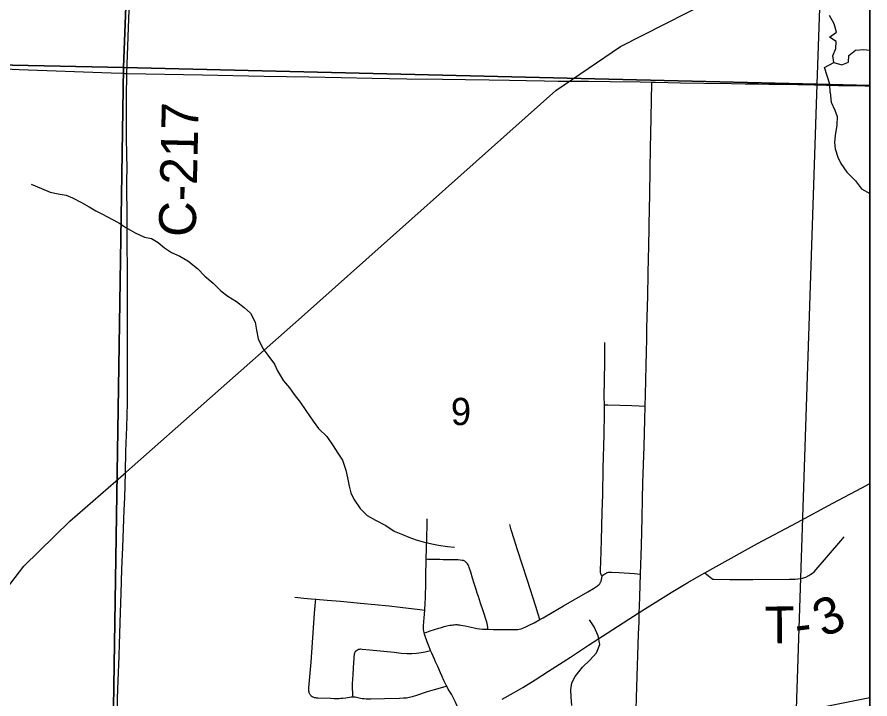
# Model space of a CAD drawing. Extents: x 0 to 34, y 0 to 22.
# Drawn here: x 7.587 to 8.9, y 18.594 to 19.643 of the extents above; entities that cross this region are included whole.
import ezdxf

# ---------------------------------------------------------------- set-up
doc = ezdxf.new("R2010")
doc.units = 0
for name, color, linetype in [('GM_X_Corporation', 7, 'Continuous'), ('GM_X_County_Road', 7, 'Continuous'), ('GM_X_County_Road_Text', 7, 'Continuous'), ('GM_X_Minor_River', 7, 'Continuous'), ('GM_X_Rail_Line', 7, 'Continuous'), ('GM_X_Section_Text', 7, 'Continuous'), ('GM_X_Township_Road', 7, 'Continuous'), ('GM_X_Township_Road_Text', 7, 'Continuous'), ('GM_X_US_Route', 7, 'Continuous'), ('SH_Data', 7, 'Continuous')]:
    doc.layers.add(name, color=color, linetype=linetype)

msp = doc.modelspace()

# ---------------------------------------------------------------- linework, layer by layer
at = {"layer": 'GM_X_Corporation'}
for points in [[(8.9, 14.4942), (8.9, 20.9), (2.1, 20.9)], [(8.9, 14.4942), (8.9, 20.5041)]]:
    msp.add_lwpolyline(points, dxfattribs=at)
for points in [[(6.788, 20.5454), (7.7872, 20.529), (7.7504, 19.5655), (6.7486, 19.5865)], [(7.7872, 20.529), (8.792, 20.506), (8.8523, 20.5047), (8.8184, 19.5395), (7.7504, 19.5655)], [(8.9, 19.5378), (8.9, 20.5036), (8.8523, 20.5047), (8.8184, 19.5395)], [(6.7486, 19.5865), (7.7504, 19.5655), (7.7346, 18.5471), (6.72, 18.5734), (6.7472, 19.5762)], [(8.8184, 19.5395), (8.7846, 18.5318), (7.7346, 18.5471), (7.7504, 19.5655)], [(8.9, 18.5295), (8.9, 19.5378), (8.8184, 19.5395), (8.7846, 18.5318)]]:
    msp.add_lwpolyline(points, close=True, dxfattribs=at)
at = {"layer": 'GM_X_County_Road'}
for points in [[(7.7558, 19.5562), (7.758, 19.6264), (7.7595, 19.6668), (7.7619, 19.7283), (7.7639, 19.7923), (7.7668, 19.8662), (7.7707, 19.9768), (7.7744, 20.0693), (7.7761, 20.1203), (7.7788, 20.1874), (7.7812, 20.2483), (7.7819, 20.2659)], [(7.7523, 18.9034), (7.7529, 18.9215), (7.7534, 18.9426), (7.7543, 18.975), (7.7555, 19.0116), (7.7564, 19.0489), (7.7567, 19.0862), (7.7567, 19.1278), (7.7568, 19.1626), (7.7568, 19.208), (7.7566, 19.2447), (7.7561, 19.3031), (7.7562, 19.3305), (7.7558, 19.3895), (7.7559, 19.4125), (7.7558, 19.4293), (7.7553, 19.4592), (7.7552, 19.4902), (7.7552, 19.5226), (7.7557, 19.5531), (7.7558, 19.5562)], [(7.7405, 18.5671), (7.7408, 18.5697), (7.741, 18.5721), (7.7413, 18.5935), (7.7418, 18.6088), (7.7423, 18.6215), (7.7438, 18.6593), (7.7441, 18.678), (7.746, 18.7265), (7.7471, 18.7563), (7.7481, 18.7929), (7.7494, 18.8271), (7.7517, 18.8842), (7.7523, 18.9034)]]:
    msp.add_lwpolyline(points, dxfattribs=at)
at = {"layer": 'GM_X_Minor_River'}
for points in [[(8.8446, 19.5732), (8.8426, 19.5835), (8.8474, 19.5948), (8.8481, 19.6054), (8.8376, 19.6121), (8.8484, 19.6198), (8.845, 19.6324), (8.8377, 19.6455)], [(8.839, 19.5269), (8.8381, 19.5399), (8.8343, 19.5525), (8.83, 19.5656), (8.8446, 19.5732), (8.8567, 19.5695), (8.867, 19.5734), (8.8677, 19.584), (8.8777, 19.5921), (8.8907, 19.5929), (8.9, 19.5921)], [(8.839, 19.5269), (8.8405, 19.5121), (8.8459, 19.4999), (8.8495, 19.4899), (8.8489, 19.4767), (8.8463, 19.4608), (8.8454, 19.4502), (8.8463, 19.4403), (8.8506, 19.4273), (8.8554, 19.4177), (8.8646, 19.4043), (8.8776, 19.3911), (8.8868, 19.3784), (8.9, 19.3717), (8.9, 19.3717)], [(7.6082, 19.3857), (7.6244, 19.3789), (7.6376, 19.3733), (7.6501, 19.3712), (7.6621, 19.3687), (7.6719, 19.3647), (7.6858, 19.3576), (7.6974, 19.3509), (7.708, 19.345), (7.7181, 19.3395), (7.7327, 19.3317), (7.7432, 19.3261), (7.7541, 19.3191), (7.7683, 19.3108), (7.783, 19.3045), (7.7936, 19.302), (7.8041, 19.2961), (7.8138, 19.2876), (7.8243, 19.2809), (7.8374, 19.275), (7.8498, 19.2679), (7.8644, 19.2559), (7.8759, 19.2442), (7.8886, 19.2337), (7.9005, 19.2218), (7.911, 19.2136), (7.9244, 19.205), (7.9364, 19.196), (7.9461, 19.1871), (7.953, 19.1733), (7.9551, 19.1611), (7.9578, 19.1478), (7.9651, 19.1328), (7.9725, 19.1228), (7.9829, 19.109), (7.9876, 19.0986), (7.9968, 19.0829), (8.0061, 19.0721), (8.0134, 19.0621), (8.0223, 19.0501), (8.0312, 19.0374), (8.0426, 19.0209), (8.0507, 19.0097), (8.0634, 18.9973), (8.0734, 18.9831), (8.0807, 18.972), (8.0877, 18.9612), (8.0931, 18.9455), (8.0952, 18.9337), (8.0979, 18.9208), (8.1008, 18.9108), (8.1051, 18.9009), (8.1147, 18.8867), (8.1259, 18.8758), (8.1386, 18.8687), (8.1544, 18.8605), (8.1675, 18.8519), (8.1799, 18.8467), (8.1901, 18.8427), (8.201, 18.8383), (8.2119, 18.8351), (8.2252, 18.8321), (8.2357, 18.83), (8.2493, 18.8279), (8.26, 18.8273)], [(8.4411, 18.5836), (8.4398, 18.5965), (8.4396, 18.6075), (8.441, 18.6185), (8.4461, 18.6282), (8.4574, 18.6424), (8.4686, 18.6532), (8.479, 18.6644), (8.4838, 18.6772), (8.4814, 18.6906), (8.4752, 18.7043), (8.4679, 18.7155)]]:
    msp.add_lwpolyline(points, dxfattribs=at)
at = {"layer": 'GM_X_Rail_Line'}
for points in [[(7.4231, 18.1406), (7.4319, 18.4427), (7.4457, 18.5085), (7.4686, 18.5744), (7.4977, 18.6464), (7.5498, 18.7367), (7.5972, 18.798), (7.6677, 18.8669), (7.7503, 18.9389), (8.0244, 19.1809), (8.4163, 19.5301), (8.5159, 19.5976), (8.7545, 19.7191), (8.8502, 19.7708), (8.9, 19.7957)], [(2.1, 17.2578), (2.1839, 17.2743), (2.7373, 17.3807), (3.3215, 17.4979), (3.9612, 17.6228), (4.5554, 17.74), (5.1565, 17.8564), (5.7754, 17.979), (6.3342, 18.0908), (6.9022, 18.2018), (7.3492, 18.2882), (7.4239, 18.3027), (8.0092, 18.4168), (8.4623, 18.5082), (8.9, 18.5958)]]:
    msp.add_lwpolyline(points, dxfattribs=at)
at = {"layer": 'GM_X_Township_Road'}
for points in [[(7.5359, 19.5647), (7.59, 19.5625), (7.6322, 19.5609), (7.7316, 19.5572), (7.749, 19.5566), (7.7528, 19.5564), (7.7558, 19.5562)], [(7.7558, 19.5562), (7.8723, 19.5539), (7.9672, 19.5521), (8.0015, 19.5515), (8.0361, 19.5508), (8.0858, 19.55), (8.1334, 19.5492), (8.1868, 19.5481), (8.2418, 19.5475), (8.2774, 19.5469), (8.3135, 19.5464), (8.3451, 19.5459), (8.3709, 19.5454), (8.3987, 19.5449), (8.4198, 19.5446), (8.4317, 19.5445), (8.446, 19.5443), (8.4665, 19.5441), (8.4998, 19.5436), (8.546, 19.5431), (8.564, 19.5428)], [(8.561, 19.3673), (8.5616, 19.4111), (8.5628, 19.4664), (8.563, 19.4851), (8.5636, 19.5175), (8.5639, 19.5386), (8.564, 19.5428)], [(8.564, 19.5428), (8.5697, 19.5427), (8.6082, 19.5418), (8.6442, 19.5412), (8.687, 19.5406), (8.7079, 19.5404), (8.7283, 19.5401), (8.7443, 19.5399), (8.7672, 19.5396), (8.7746, 19.5395), (8.7889, 19.5392), (8.8144, 19.5386), (8.8517, 19.5379), (8.8927, 19.5372), (8.9, 19.5371)], [(8.5539, 19.0441), (8.5544, 19.0615), (8.5556, 19.1065), (8.556, 19.1276), (8.5563, 19.1475), (8.5566, 19.1643), (8.5578, 19.2137), (8.5587, 19.2476), (8.5591, 19.2719), (8.5595, 19.2895), (8.5607, 19.3504), (8.561, 19.3673)], [(8.4911, 19.0463), (8.4907, 19.0587), (8.4916, 19.1115), (8.4919, 19.1327), (8.4918, 19.142)], [(8.4874, 18.7825), (8.4867, 18.7837), (8.4861, 18.785), (8.4857, 18.786), (8.4854, 18.7867), (8.4853, 18.7874), (8.4852, 18.7884), (8.4851, 18.7903), (8.4851, 18.792), (8.4854, 18.8044), (8.4864, 18.8374), (8.4877, 18.8815), (8.4884, 18.9076), (8.4894, 18.9486), (8.4906, 19.0002), (8.4912, 19.0338), (8.4911, 19.045), (8.4911, 19.0463)], [(8.4911, 19.0463), (8.4964, 19.0461), (8.5332, 19.0452), (8.5445, 19.0446), (8.5539, 19.0441)], [(8.5467, 18.7858), (8.548, 18.8299), (8.5493, 18.8722), (8.5499, 18.9008), (8.5505, 18.9262), (8.5521, 18.9822), (8.5532, 19.0238), (8.5539, 19.0441)], [(8.2165, 18.8084), (8.2175, 18.8424), (8.2179, 18.861), (8.2182, 18.8709)], [(8.3918, 18.7158), (8.3893, 18.7241), (8.3856, 18.736), (8.3728, 18.7756), (8.3649, 18.7992), (8.3573, 18.8228), (8.3521, 18.8394), (8.3475, 18.854), (8.3453, 18.8618)], [(8.6459, 18.7878), (8.6514, 18.7832), (8.6566, 18.7789), (8.658, 18.7781), (8.6595, 18.7778), (8.6844, 18.7773), (8.7198, 18.7775), (8.7761, 18.7777), (8.7848, 18.7781), (8.793, 18.779), (8.7962, 18.7795), (8.8013, 18.7809), (8.8058, 18.7833), (8.8089, 18.7854), (8.8115, 18.7871), (8.814, 18.7894), (8.8173, 18.7925), (8.8554, 18.8369), (8.8605, 18.8432)], [(8.2145, 18.73), (8.2146, 18.7313), (8.2151, 18.7399), (8.2155, 18.7499), (8.2161, 18.7716), (8.2161, 18.7796), (8.2162, 18.7834), (8.2164, 18.8076), (8.2165, 18.8084)], [(8.3118, 18.7007), (8.3115, 18.7034), (8.3108, 18.7072), (8.3103, 18.7097), (8.3094, 18.7133), (8.3042, 18.7293), (8.3004, 18.7411), (8.2986, 18.7463), (8.297, 18.7511), (8.2953, 18.7563), (8.2934, 18.7622), (8.2906, 18.7712), (8.2881, 18.7794), (8.2853, 18.7885), (8.283, 18.7958), (8.2821, 18.7979), (8.2813, 18.7998), (8.28, 18.8017), (8.2788, 18.8032), (8.2776, 18.8042), (8.2768, 18.8049), (8.276, 18.8054), (8.275, 18.8059), (8.274, 18.8064), (8.2719, 18.8068), (8.269, 18.8071), (8.2656, 18.8074), (8.2616, 18.8075), (8.2516, 18.8077), (8.243, 18.8078), (8.2374, 18.8079), (8.2337, 18.808), (8.2294, 18.808), (8.2191, 18.8083), (8.2165, 18.8084)], [(8.3918, 18.7158), (8.3966, 18.7184), (8.4105, 18.7267), (8.4282, 18.737), (8.4655, 18.7584), (8.4741, 18.7635), (8.4789, 18.7665), (8.4803, 18.7675), (8.4817, 18.7686), (8.4828, 18.7696), (8.4839, 18.7708), (8.4845, 18.7718), (8.4852, 18.773), (8.4856, 18.7739), (8.4859, 18.7748), (8.4864, 18.7773), (8.4869, 18.7797), (8.4874, 18.7825)], [(8.4874, 18.7825), (8.4888, 18.7838), (8.4903, 18.785), (8.4916, 18.786), (8.4927, 18.7867), (8.4942, 18.7876), (8.4951, 18.788), (8.496, 18.7883), (8.4975, 18.7886), (8.4992, 18.7888), (8.5018, 18.7888), (8.5137, 18.7883), (8.5373, 18.7867), (8.5422, 18.7862), (8.5467, 18.7858)], [(8.5448, 18.7266), (8.5451, 18.7357), (8.5456, 18.7511), (8.5467, 18.7858)], [(8.0142, 18.75), (8.0284, 18.7485), (8.0394, 18.7474), (8.0469, 18.7469)], [(8.0386, 18.5994), (8.0379, 18.6002), (8.0373, 18.601), (8.0367, 18.602), (8.0364, 18.6029), (8.0362, 18.6037), (8.036, 18.6053), (8.0359, 18.6067), (8.0361, 18.6108), (8.0393, 18.6503), (8.0446, 18.7254), (8.0457, 18.7369), (8.0464, 18.7432), (8.0469, 18.7469)], [(8.0469, 18.7469), (8.0643, 18.7457), (8.0847, 18.7438), (8.1156, 18.741), (8.1594, 18.7366), (8.1767, 18.7347), (8.2069, 18.731), (8.2145, 18.73)], [(8.2135, 18.6951), (8.2133, 18.696), (8.2129, 18.6979), (8.2125, 18.7004), (8.2123, 18.7028), (8.2123, 18.7059), (8.2129, 18.7121), (8.2135, 18.7183), (8.2145, 18.73)], [(8.5382, 18.5205), (8.5384, 18.5279), (8.5388, 18.5434), (8.5389, 18.549), (8.5394, 18.5606), (8.5411, 18.6123), (8.5436, 18.6932), (8.5444, 18.7121), (8.5448, 18.7266)], [(8.2135, 18.6951), (8.2175, 18.6965), (8.2228, 18.6983), (8.2359, 18.7023), (8.24, 18.7036), (8.2444, 18.7048), (8.2486, 18.7059), (8.253, 18.7068), (8.2556, 18.7073), (8.2574, 18.7075), (8.2598, 18.7078), (8.262, 18.708), (8.2639, 18.7079), (8.2656, 18.7078), (8.2678, 18.7076), (8.2699, 18.7073), (8.2766, 18.706), (8.2905, 18.7028), (8.2945, 18.702), (8.2989, 18.7013), (8.3032, 18.7009), (8.3073, 18.7007), (8.3118, 18.7007)], [(8.3118, 18.7007), (8.3198, 18.7006), (8.3257, 18.7005), (8.3325, 18.7004), (8.3364, 18.7003), (8.3405, 18.7002), (8.3432, 18.7002), (8.3456, 18.7002), (8.3479, 18.7002), (8.3518, 18.7002), (8.355, 18.7003), (8.3578, 18.7005), (8.3599, 18.7009), (8.3627, 18.7015), (8.3657, 18.7024), (8.3702, 18.7044), (8.3752, 18.7068), (8.383, 18.7108), (8.3918, 18.7158)], [(8.2235, 18.668), (8.2228, 18.6698), (8.221, 18.6738), (8.2179, 18.6813), (8.2149, 18.6901), (8.214, 18.6931), (8.2135, 18.6951)], [(8.104, 18.5968), (8.1039, 18.5989), (8.1036, 18.6029), (8.1033, 18.6096), (8.1033, 18.6166), (8.1041, 18.6313), (8.1053, 18.6503), (8.1056, 18.6546), (8.1059, 18.6588), (8.1061, 18.6613), (8.1064, 18.663), (8.1068, 18.6645), (8.1072, 18.6653), (8.108, 18.6669), (8.1086, 18.6677), (8.1093, 18.6683), (8.1108, 18.6693)], [(8.1108, 18.6693), (8.1126, 18.6699), (8.1145, 18.6703), (8.1162, 18.6704), (8.1182, 18.6703), (8.13, 18.6693), (8.1671, 18.6653), (8.1782, 18.6642), (8.1869, 18.6637), (8.1943, 18.6636), (8.2018, 18.6641), (8.2053, 18.6644), (8.2087, 18.6648), (8.2119, 18.6653), (8.2151, 18.6659), (8.221, 18.6674), (8.2235, 18.668)], [(8.2483, 18.613), (8.2474, 18.6147), (8.2457, 18.618), (8.2439, 18.622), (8.2412, 18.6282), (8.2386, 18.6337), (8.2343, 18.6433), (8.2312, 18.6507), (8.2295, 18.6546), (8.2253, 18.6642), (8.224, 18.667), (8.2235, 18.668)], [(8.104, 18.5968), (8.1061, 18.5968), (8.1073, 18.5967), (8.1091, 18.5964), (8.1157, 18.5948), (8.118, 18.5944), (8.1209, 18.5941), (8.1242, 18.5938), (8.1275, 18.5937), (8.1313, 18.5937), (8.1524, 18.5941), (8.1754, 18.5945), (8.1817, 18.595), (8.1861, 18.5954), (8.1904, 18.5962), (8.1957, 18.5975), (8.2024, 18.5995), (8.2188, 18.6048), (8.2295, 18.6079), (8.246, 18.6124), (8.2483, 18.613)], [(8.2694, 18.5671), (8.2667, 18.5753), (8.2643, 18.5824), (8.2618, 18.5887), (8.2587, 18.5948), (8.2554, 18.6007), (8.2506, 18.6087), (8.2494, 18.6109), (8.2483, 18.613)], [(8.0386, 18.5994), (8.0394, 18.5985), (8.041, 18.5972), (8.042, 18.5965), (8.0429, 18.5962), (8.044, 18.5958), (8.0456, 18.5955), (8.0473, 18.5953), (8.0497, 18.5951), (8.0691, 18.5945), (8.075, 18.5944), (8.0794, 18.5943), (8.0824, 18.5944), (8.0853, 18.5945), (8.0883, 18.5947), (8.0928, 18.5954), (8.1013, 18.5967), (8.1027, 18.5968), (8.104, 18.5968)]]:
    msp.add_lwpolyline(points, dxfattribs=at)
at = {"layer": 'GM_X_US_Route'}
for points in [[(8.5448, 18.7266), (8.594, 18.7571), (8.6195, 18.7725), (8.6399, 18.7844), (8.6459, 18.7878), (8.6632, 18.7976), (8.727, 18.8326), (8.7878, 18.8652), (8.8426, 18.8946), (8.8876, 18.9186), (8.9, 18.9252)], [(8.4052, 18.6361), (8.4387, 18.6576), (8.4667, 18.6761), (8.4954, 18.6946), (8.5448, 18.7266)], [(8.3338, 18.5931), (8.3513, 18.6027), (8.3652, 18.6109), (8.3842, 18.6227), (8.4052, 18.6361)]]:
    msp.add_lwpolyline(points, dxfattribs=at)
at = {"layer": 'SH_Data'}
msp.add_line((8.9, 20.9), (8.9, 14.1), dxfattribs=at)

# ---------------------------------------------------------------- texts
at = {"layer": 'GM_X_County_Road_Text'}
msp.add_text('C-217', height=0.05682, rotation=88.6312, dxfattribs=at).set_placement((7.8615, 19.3041))
at = {"layer": 'GM_X_Section_Text'}
msp.add_text('9', height=0.0419, rotation=0, dxfattribs=at).set_placement((8.2546, 19.015))
at = {"layer": 'GM_X_Township_Road_Text'}
for s, rotation, p in [('3', 24.1965, (8.8285, 18.6874)), ('T', 0.5571, (8.738, 18.6788)), ('-', 6.7882, (8.7872, 18.6797))]:
    msp.add_text(s, height=0.0568, rotation=rotation, dxfattribs=at).set_placement(p)

doc.saveas('drawing.dxf')
